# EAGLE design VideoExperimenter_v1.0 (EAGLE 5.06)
DRAWING_NAME: Video Experimenter Shield
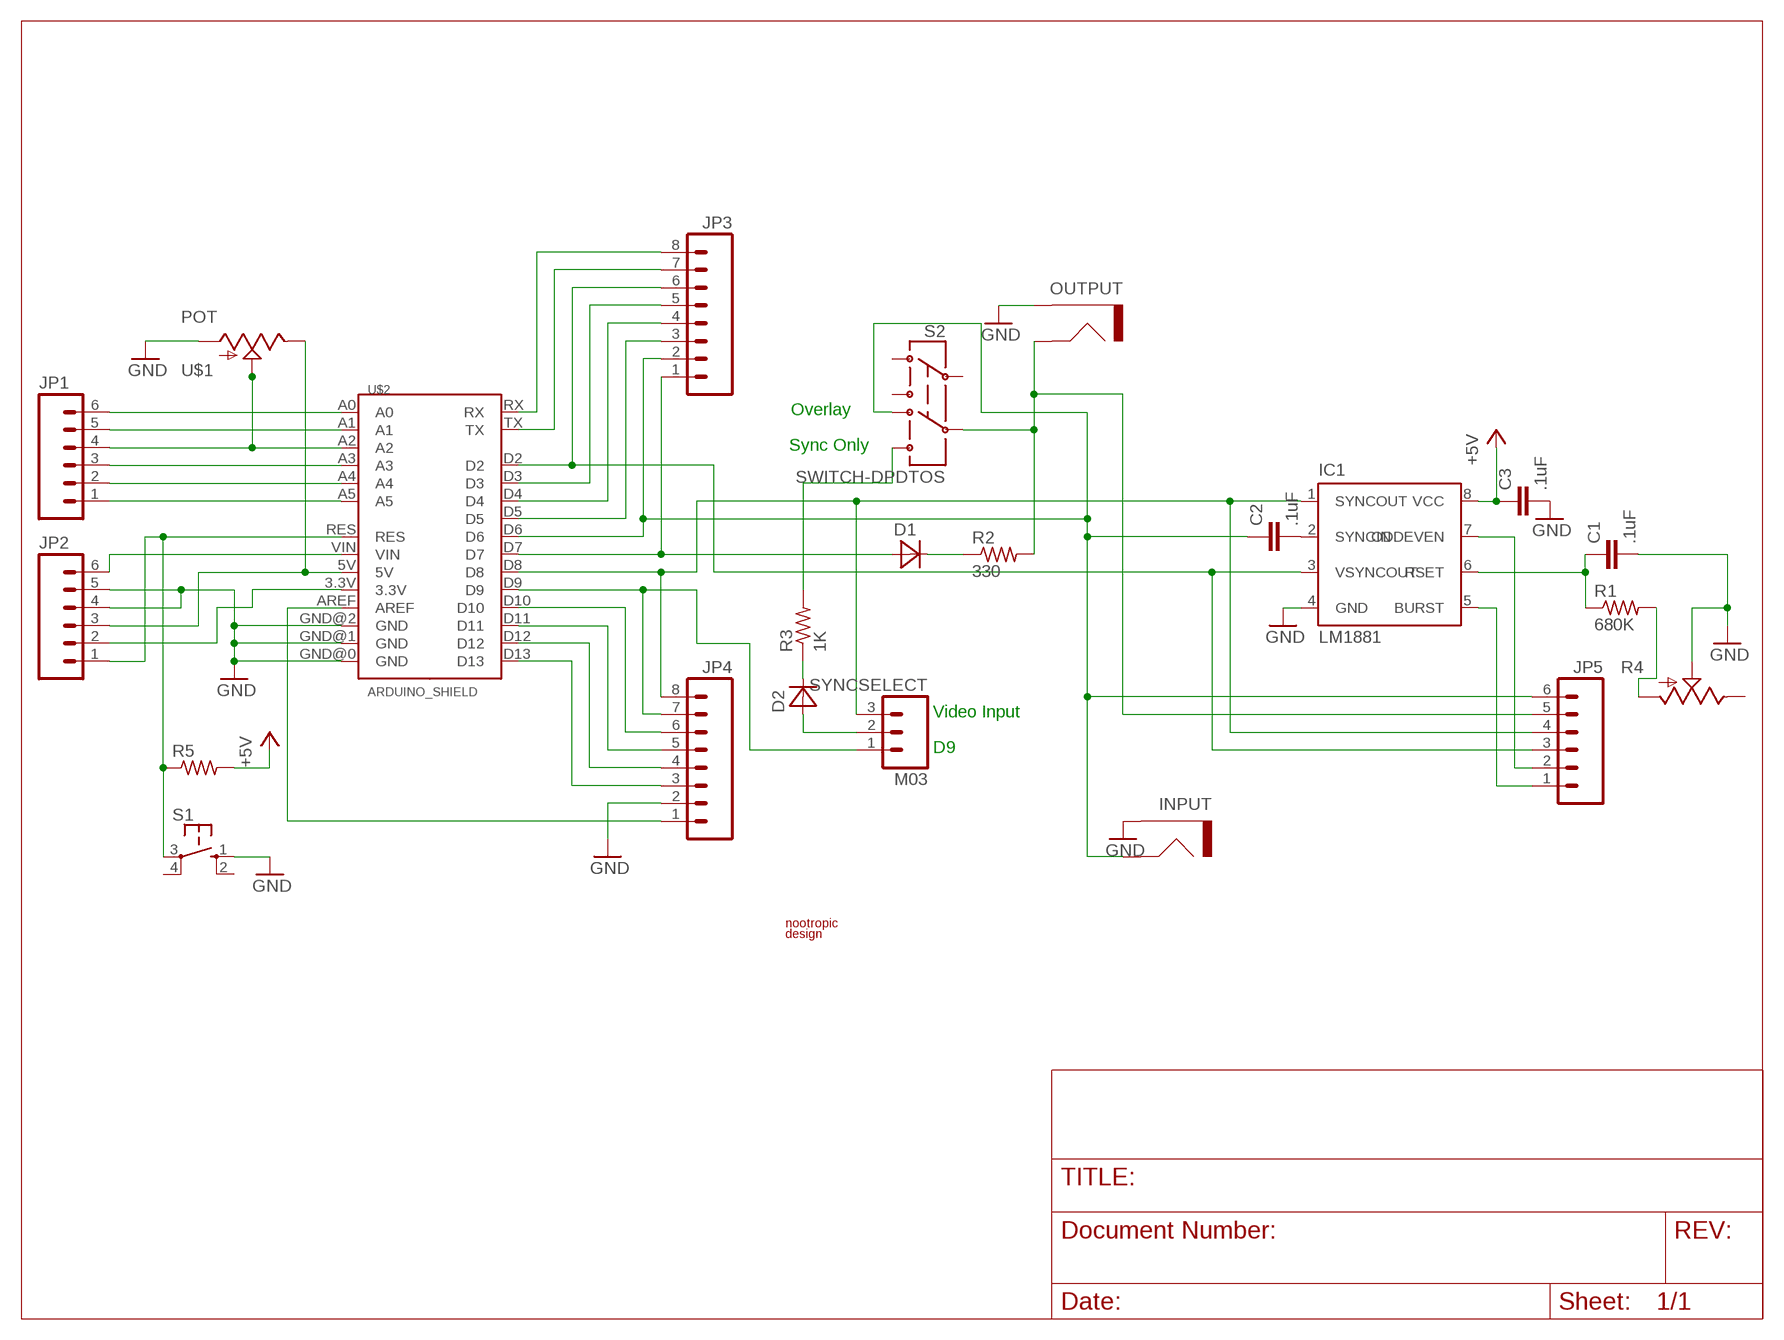
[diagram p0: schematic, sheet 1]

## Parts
C1  .1uF  CAPSMALL  [CAP-CERAMIC-SMALL]
C2  .1uF  CAPSMALL  [CAP-CERAMIC-SMALL]
C3  .1uF  CAPSMALL  [CAP-CERAMIC-SMALL]
D1  1N4148  [D35-10]
D2  1N4148  [D35-10]
IC1  LM1881  [DIL08]
INPUT  RCAJACK  [RCA]
JP1  M06  [1X06]
JP2  M06  [1X06]
JP3  M08  [1X08]
JP4  M08  [1X08]
JP5  M06  [1X06]
OUTPUT  RCAJACK  [RCA]
R1  680K  R-US  [0207/10]
R2  330  R-US  [0207/10]
R3  1K  R-US  [0207/10]
R4  POTTRIM  [TRIM_POT]
R5  R-US  [0207/10]
S1  SWITCH-TACT  [SWITCH-TACT]
S2  SWITCH-DPDTOS  [OS]
SYNCSELECT  M03  [1X03]
U$1  POT  [TRIMMERPOT]
U$2  ARDUINO_SHIELD  [DUEMILANOVE_SHIELD]
U$3  LOGO  [LOGO_SMALL]

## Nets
+5V: C3.1 IC1.8(VCC) JP2.3 R5.2 U$1.3 U$2.5V
A0: JP1.6 U$2.A0
A1: JP1.5 U$2.A1
A2: JP1.4 U$1.2(WIPER) U$1.4(WIPER) U$2.A2
A3: JP1.3 U$2.A3
A4: JP1.2 U$2.A4
A5: JP1.1 U$2.A5
BURST: IC1.5(BURST) JP5.1
D3: JP3.5 U$2.D3
D4: JP3.4 U$2.D4
D5: JP3.3 U$2.D5
D9: JP4.7 SYNCSELECT.1 U$2.D9
D10: JP4.6 U$2.D10
D11: JP4.5 U$2.D11
D12: JP4.4 U$2.D12
D13: JP4.3 U$2.D13
GND: C1.2 C3.2 IC1.4(GND) INPUT.BARREL(GND) JP2.4 JP2.5 JP4.2 OUTPUT.BARREL(GND) R4.1(S) S1.1(S) U$1.1 U$2.GND@0(GND) U$2.GND@1(GND) U$2.GND@2(GND)
N$1: R3.2 S2.6
N$3: D1.C R2.1
N$4: R1.2 R4.3(A)
N$8: D2.C R3.1
N$13: D2.A SYNCSELECT.2
N$14: JP2.2 U$2.3.3V
N$19: JP3.7 U$2.TX
N$20: JP3.8 U$2.RX
N$26: JP4.1 U$2.AREF
N$29: C2.2 IC1.2(SYNCIN)
ODD/EVEN: IC1.7(ODDEVEN) JP5.2
RESET: JP2.1 R5.1 S1.3(P) U$2.RES
RSET: C1.1 IC1.6(RSET) R1.1
SYNCOUT: IC1.1(SYNCOUT) JP4.8 JP5.4 SYNCSELECT.3 U$2.D8
VIDEOINPUT: C2.1 INPUT.P$2(SIGNAL) JP3.2 JP5.6 S2.4 U$2.D6
VIDEOOUT: D1.A JP3.1 U$2.D7
VIDEOOUTPUT: JP5.5 OUTPUT.P$2(SIGNAL) R2.2 S2.5
VIN: JP2.6 U$2.VIN
VSYNC: IC1.3(VSYNCOUT) JP3.6 JP5.3 U$2.D2
Unconnected: R4.2(E) S1.2(S1) S1.4(P1) S2.1 S2.2 S2.3

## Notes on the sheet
- Overlay
- Sync Only
- Video Input
- D9

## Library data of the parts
C1-C3 = nootropicdesign:CAP: Unpolarized capacitor
D1 D2 = nootropicdesign:1N4148
IC1 = lm1881:LM1881
INPUT OUTPUT = nootropicdesign:RCAJACK: RCA jack
JP1 JP2 JP5 = nootropicdesign:M06: 6-pin header
JP3 JP4 = nootropicdesign:M08: 8-pin header
R1-R3 R5 = nootropicdesign:R-US: Resistor
R4 = SparkFun:POT
S1 = nootropicdesign:SWITCH-TACT: 12MM Tactile Switch
S2 = SparkFun:SWITCH-DPDT: DPDT Version of the COM-00597
SYNCSELECT = nootropicdesign:M03
U$1 = nootropicdesign:POT
U$2 = nootropicdesign:ARDUINO_SHIELD
U$3 = nootropicdesign:LOGO

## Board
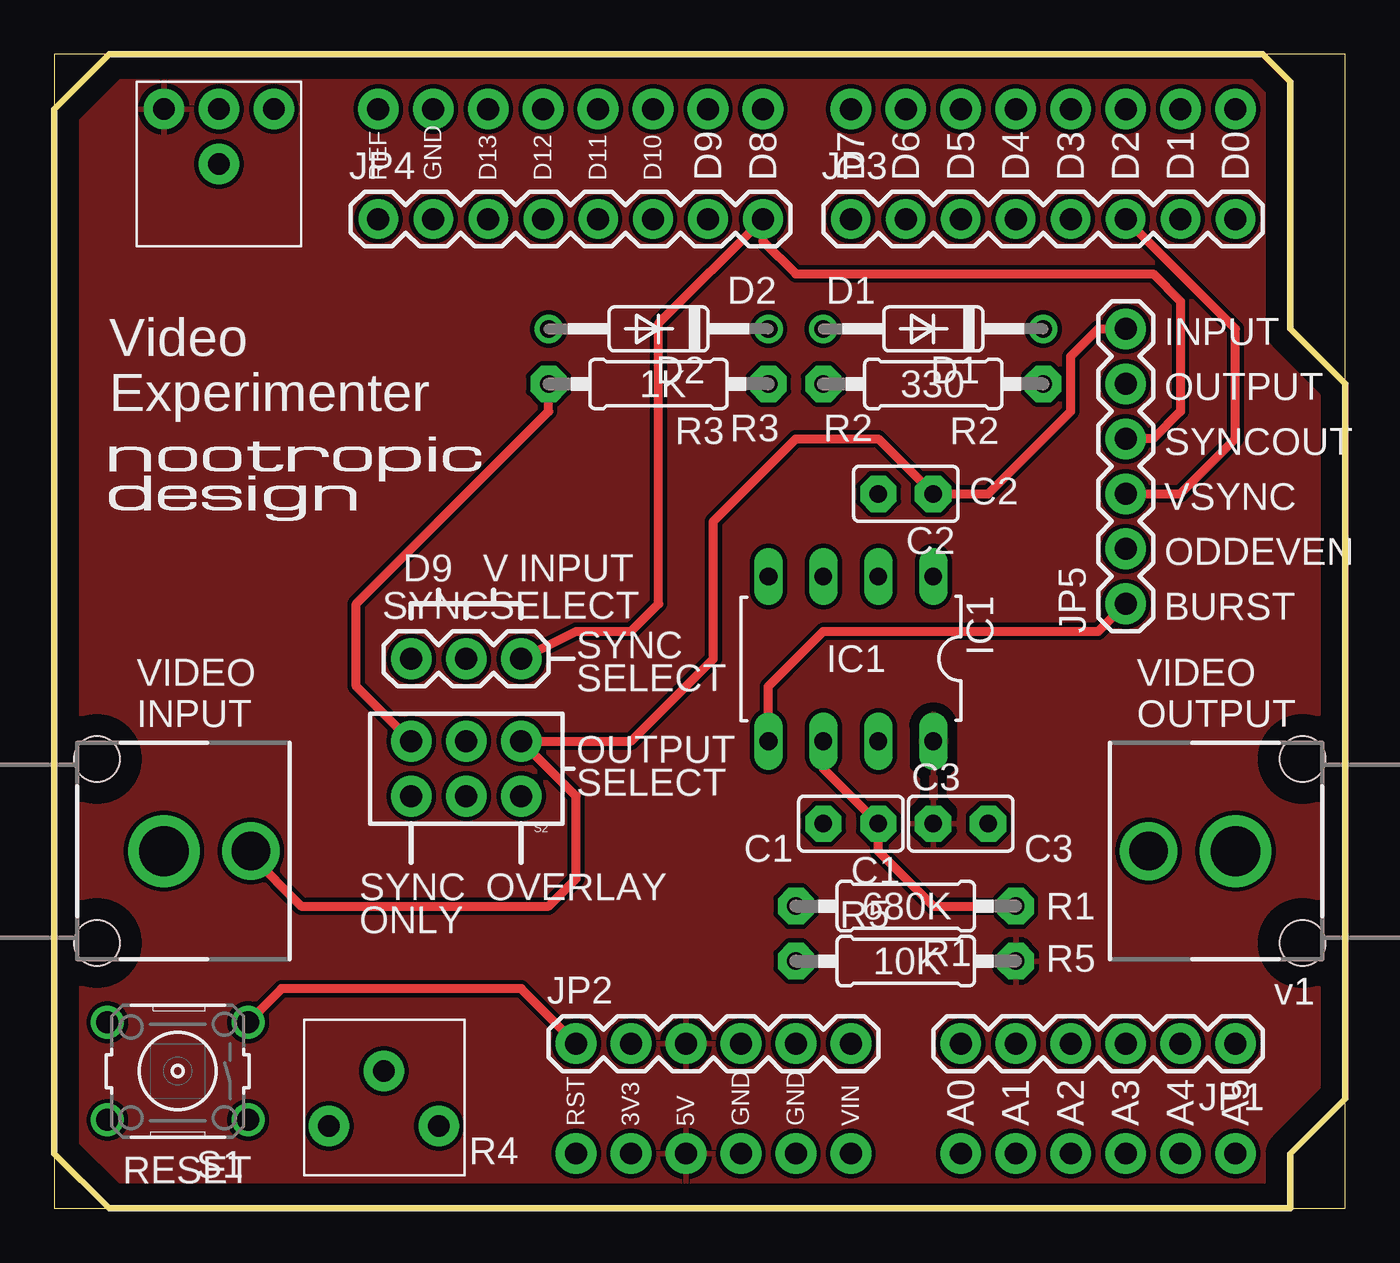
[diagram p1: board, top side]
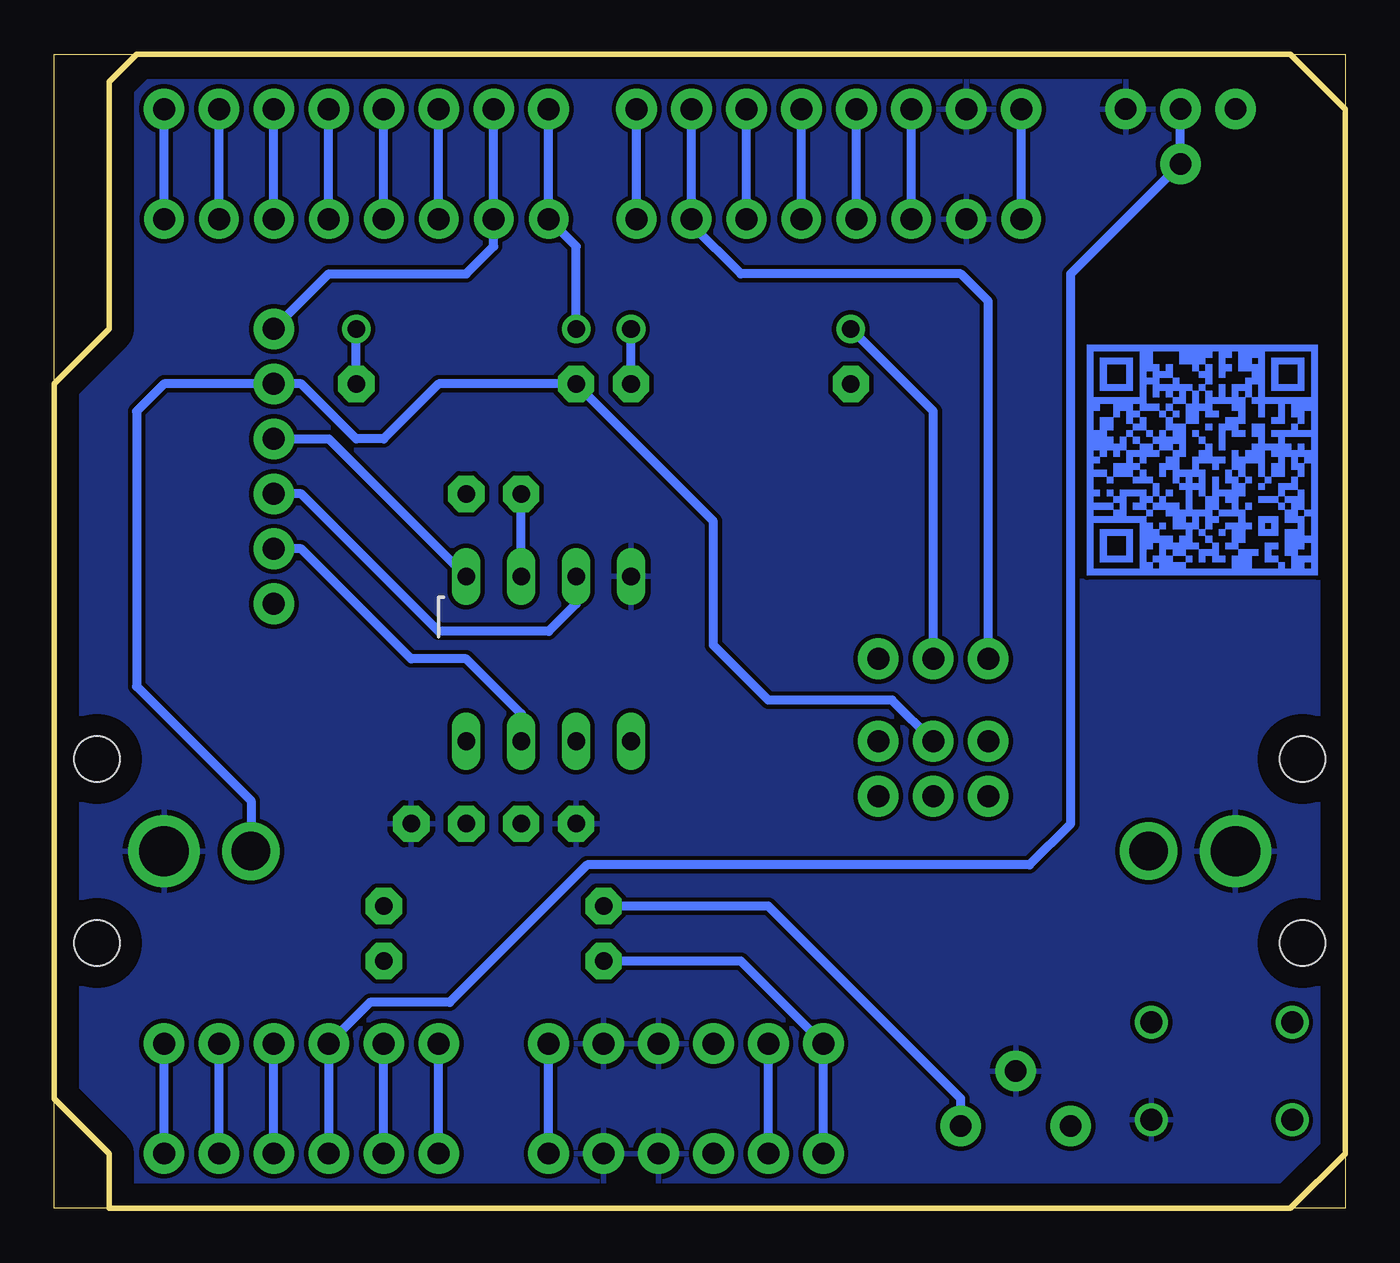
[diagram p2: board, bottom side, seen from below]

Size 59.69 x 53.34 mm. Coordinates in mm from the lower left corner, seen from the top.
Outline: 2.54,0 0,0 0,2.54
Outline: 57.15,0 59.69,0 59.69,53.34 0,53.33 0,50.8
Outline: 0,50.8 2.54,53.34 55.88,53.34 57.15,52.07 57.15,40.64 59.69,38.1 59.69,5.08 57.15,2.54 57.15,0
Outline: 57.15,0 2.54,0
Outline: 2.54,0 0,2.54
Outline: 0,2.54 0,50.8
Copper layers (1*16): Top 0.035mm / dielectric 1.5mm / Bottom 0.035mm
Design rules "default": minimum track width 10mil, minimum drill 24mil, track to track 8mil, track to pad 8mil, pad to pad 8mil, via to via 8mil, smd to smd 8mil, copper to edge 40mil, drill to drill 8mil, minimum pad ring 10mil, minimum via ring 8mil, stop-mask expansion 4mil, vias tented up to drill 0mil, thermal gap 10mil
tRestrict: 9 lines

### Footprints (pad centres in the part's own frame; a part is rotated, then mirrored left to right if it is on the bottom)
CAP-CERAMIC-SMALL = drill 0.813 pad 1.676 octagon: 1 -1.27,0; 2 1.27,0
D35-10 = drill 0.813 round: A 5.08,0; C -5.08,0
DIL08 = drill 0.813 long: 1 -3.81,-3.81; 2 -1.27,-3.81; 3 1.27,-3.81; 4 3.81,-3.81; 5 3.81,3.81; 6 1.27,3.81; 7 -1.27,3.81; 8 -3.81,3.81
RCA = drill 2.3 round: BARREL 0,0 | drill 1.778 pad 2.54 round: P$2 4.02,0.002 | hole 2.1: -3.1,4.25; -3.1,-4.25
1X06 = drill 1.016 pad 1.88 round: 1 0,0; 2 2.54,0; 3 5.08,0; 4 7.62,0; 5 10.16,0; 6 12.7,0
1X08 = drill 1.016 pad 1.829 round: 1 0,0; 2 2.54,0; 3 5.08,0; 4 7.62,0; 5 10.16,0; 6 12.7,0; 7 15.24,0; 8 17.78,0
0207/10 = drill 0.813 pad 1.676 octagon: 1 -5.08,0; 2 5.08,0
TRIM_POT = drill 1 pad 1.88 round: 1 2.54,0; 2 0,2.54; 3 0,-2.54
SWITCH-TACT = drill 1.016 round: 1 -3.251,2.261; 2 3.251,2.261; 3 -3.251,-2.261; 4 3.251,-2.261
OS = drill 1.016 pad 1.88 round: 1 -2.54,1.27; 2 0,1.27; 3 2.54,1.27; 4 -2.54,-1.27; 5 0,-1.27; 6 2.54,-1.27
1X03 = drill 1.016 pad 1.88 round: 1 -2.54,0; 2 0,0; 3 2.54,0
TRIMMERPOT = drill 1 pad 1.88 round: 1 2.54,-2.54; 2 2.54,0; 3 2.54,2.54; 4 0,0
DUEMILANOVE_SHIELD = drill 1.016 pad 1.88 round: 3.3V 26.67,2.54; 5V 29.21,2.54; A0 41.91,2.54; A1 44.45,2.54; A2 46.99,2.54; A3 49.53,2.54; A4 52.07,2.54; A5 54.61,2.54; AREF 14.986,50.8; D2 49.53,50.8; D3 46.99,50.8; D4 44.45,50.8; D5 41.91,50.8; D6 39.37,50.8; D7 36.83,50.8; D8 32.766,50.8; D9 30.226,50.8; D10 27.686,50.8; D11 25.146,50.8; D12 22.606,50.8; D13 20.066,50.8; GND@0 31.75,2.54; GND@1 34.29,2.54; GND@2 17.526,50.8; RES 24.13,2.54; RX 54.61,50.8; TX 52.07,50.8; VIN 36.83,2.54

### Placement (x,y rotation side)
C1  36.83,17.78 180 top
C2  39.37,33.02 180 top
C3  41.91,17.78 0 top
D1  40.64,40.64 180 top
D2  27.94,40.64 180 top
IC1  36.83,25.4 180 top
INPUT  5.08,16.51 0 top
JP1  54.61,7.62 180 top
JP2  24.13,7.62 0 top
JP3  36.83,45.72 0 top
JP4  14.99,45.72 0 top
JP5  49.53,27.94 90 top
OUTPUT  54.61,16.51 180 top
R1  39.37,13.97 180 top
R2  40.64,38.1 180 top
R3  27.94,38.1 180 top
R4  15.24,3.81 90 top
R5  39.37,11.43 0 top
S1  5.71,6.35 180 top
S2  19.05,20.32 180 top
SYNCSELECT  19.05,25.4 0 top
U$1  7.62,48.26 90 top
U$2  0,0 0 top
U$3  2.54,31.75 0 top
U$4  SECRET  [SECRET1]  1.27,29.21 0 top

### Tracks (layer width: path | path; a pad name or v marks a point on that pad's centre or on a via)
+5V
  pour Top: 2.54,52.83 0.51,50.8 0.38,50.67 0.38,2.67 2.67,0.38 56.77,0.38 56.77,2.67 59.31,5.21 59.31,37.97 56.77,40.51 56.77,51.94 55.75,52.96 2.67,52.96
A0
  Bottom 0.406: U$2.A0 JP1.6
A1
  Bottom 0.406: U$2.A1 JP1.5
A2
  Bottom 0.406: JP1.4 U$2.A2 JP1.4 | JP1.4 45.09,9.53 41.4,9.53 35.05,15.88 14.61,15.88 12.7,17.78 12.7,43.18 U$1.4 U$1.2
A3
  Bottom 0.406: U$2.A3 JP1.3
A4
  Bottom 0.406: U$2.A4 JP1.2
A5
  Bottom 0.406: U$2.A5 JP1.1
BURST
  Top 0.406: IC1.5 33.02,24.13 35.56,26.67 48.26,26.67 JP5.1
D3
  Bottom 0.406: JP3.5 U$2.D3
D4
  Bottom 0.406: JP3.4 U$2.D4
D5
  Bottom 0.406: JP3.3 U$2.D5
D9
  Bottom 0.406: U$2.D9 JP4.7 30.23,45.47 27.94,43.18 17.78,43.18 16.51,41.91 SYNCSELECT.1
D10
  Bottom 0.406: JP4.6 U$2.D10
D11
  Bottom 0.406: JP4.5 U$2.D11
D12
  Bottom 0.406: JP4.4 U$2.D12
D13
  Bottom 0.406: JP4.3 U$2.D13
GND
  pour Bottom: 0.38,50.67 0.38,2.67 0.51,2.54 2.67,0.38 56.77,0.38 56.77,2.67 59.31,5.21 59.31,37.97 56.77,40.51 56.77,51.94 55.75,52.96 2.67,52.96
N$1
  Top 0.406: R3.2 22.86,36.83 13.97,27.94 13.97,24.13 S2.6
N$3
  Bottom 0.406: R2.1 D1.C
N$4
  Bottom 0.406: R1.2 26.67,13.97 17.78,5.08 R4.3
N$8
  Bottom 0.406: R3.1 D2.C
N$13
  Bottom 0.406: D2.A 19.05,36.83 SYNCSELECT.2
N$14
  Bottom 0.406: U$2.3.3V JP2.2
N$19
  Bottom 0.406: JP3.7 U$2.TX
N$20
  Bottom 0.406: JP3.8 U$2.RX
N$26
  Bottom 0.406: JP4.1 U$2.AREF
N$29
  Bottom 0.406: IC1.2 C2.2
ODD/EVEN
  Bottom 0.406: IC1.7 38.1,22.86 40.64,25.4 43.18,25.4 48.26,30.48 JP5.2
RESET
  Top 0.406: JP2.1 21.59,10.16 10.52,10.16 S1.3
  Bottom 0.406: U$2.RES JP2.1 27.94,11.43 R5.1
RSET
  Top 0.406: IC1.6 35.56,20.32 C1.1 38.1,16.51 40.64,13.97 R1.1
SYNCOUT
  Top 0.406: JP5.4 50.8,35.56 52.07,36.83 52.07,41.91 50.8,43.18 34.29,43.18 32.77,44.7 JP4.8 27.94,40.89 27.94,27.94 26.67,26.67 24.13,26.67 SYNCSELECT.3
  Bottom 0.406: JP4.8 U$2.D8 | IC1.1 46.99,35.56 JP5.4
VIDEOINPUT
  Top 0.406: INPUT.P$2 9.1,16.3 11.43,13.97 22.86,13.97 24.13,15.24 24.13,19.05 S2.4 26.67,21.59 30.48,25.4 30.48,31.75 34.29,35.56 38.1,35.56 C2.1 43.18,33.02 46.99,36.83 46.99,39.37 48.26,40.64 JP5.6
  Bottom 0.406: U$2.D6 JP3.2 39.37,44.45 40.64,43.18 46.99,43.18 JP5.6
VIDEOOUT
  Bottom 0.406: U$2.D7 JP3.1 35.56,44.45 D1.A
VIDEOOUTPUT
  Bottom 0.406: OUTPUT.P$2 50.59,18.84 55.88,24.13 55.88,36.83 54.61,38.1 JP5.5 48.26,38.1 45.72,35.56 44.45,35.56 41.91,38.1 R2.2 29.21,31.75 29.21,26.04 26.67,23.5 20.95,23.5 S2.5
VIN
  Bottom 0.406: U$2.VIN JP2.6
VSYNC
  Top 0.406: JP3.6 54.61,40.64 54.61,35.56 52.07,33.02 JP5.3
  Bottom 0.406: JP3.6 U$2.D2 | IC1.3 35.56,27.94 36.83,26.67 41.91,26.67 48.26,33.02 JP5.3

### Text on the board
tPlace: D2 | D1 | INPUT | Video | Experimenter | 1K | 330 | OUTPUT | R3 | R2 | SYNCOUT | C2 | VSYNC | ODDEVEN | D9 | V | INPUT | BURST | SYNC | IC1 | VIDEO | SELECT | VIDEO | INPUT | OUTPUT | OUTPUT | SELECT | C1 | C3 | SYNC | OVERLAY | ONLY | 680K | R1 | 10K | R5 | v1 | R4 | RESET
